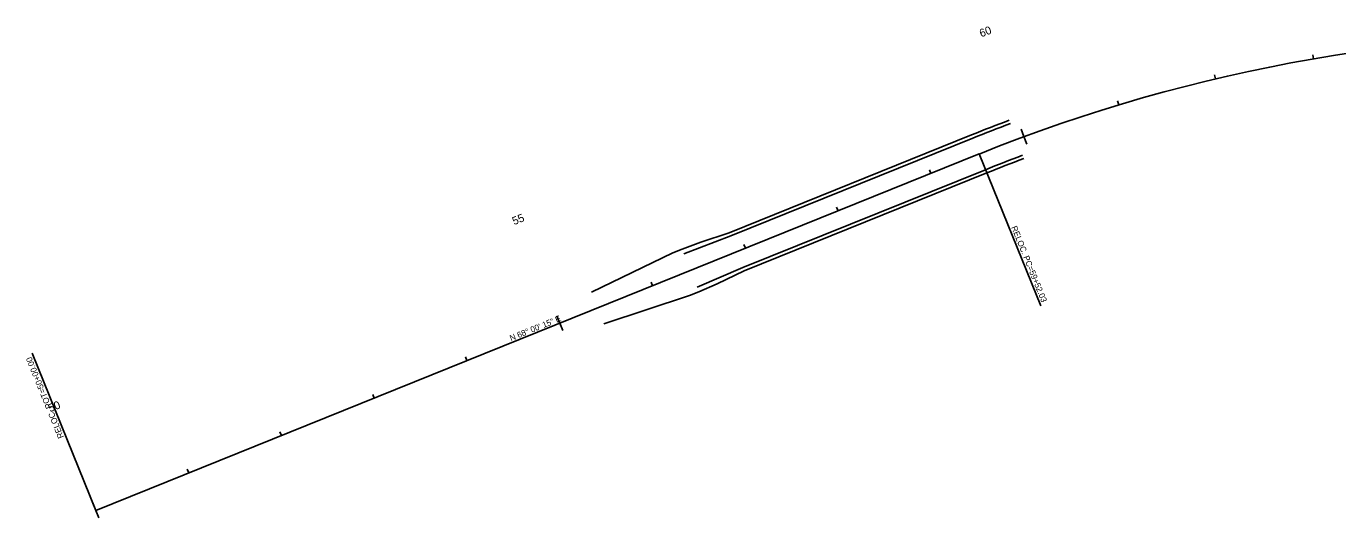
# Model space of a CAD drawing. Extents: x 1966701 to 1969286, y 1117441 to 1118086.
# Drawn here: x 1966701 to 1968012, y 1117441 to 1117933 of the extents above; entities that cross this region are included whole.
import ezdxf

# ---------------------------------------------------------------- set-up
doc = ezdxf.new("R2010")
doc.units = 0
for name, color, linetype in [('Level 19', 7, 'Continuous'), ('Level 27', 7, 'Continuous'), ('Level 35', 7, 'Continuous'), ('Level 39', 7, 'Continuous')]:
    doc.layers.add(name, color=color, linetype=linetype)

msp = doc.modelspace()

# ---------------------------------------------------------------- linework, layer by layer
at = {"layer": 'Level 19'}
for p, q in [((1967987.5, 1117899.9), (1967986.8, 1117903.8)), ((1967889.5, 1117879.8), (1967888.6, 1117883.7)), ((1967793, 1117853.8), (1967791.8, 1117857.7)), ((1967698.2, 1117822), (1967695.4, 1117829.5)), ((1967698.2, 1117822), (1967701, 1117814.5)), ((1966770.7, 1117448.1), (1967653.5, 1117804.7)), ((1967605.2, 1117785.2), (1967603.7, 1117788.9)), ((1967512.5, 1117747.7), (1967511, 1117751.5)), ((1967419.8, 1117710.3), (1967418.3, 1117714)), ((1967327.1, 1117672.8), (1967325.6, 1117676.5)), ((1967234.3, 1117635.4), (1967231.3, 1117642.8)), ((1967234.3, 1117635.4), (1967237.3, 1117628)), ((1967141.6, 1117597.9), (1967140.1, 1117601.6)), ((1967048.9, 1117560.5), (1967047.4, 1117564.2)), ((1966956.2, 1117523), (1966954.7, 1117526.7)), ((1966863.5, 1117485.6), (1966862, 1117489.3)), ((1966770.7, 1117448.1), (1966767.7, 1117455.5)), ((1966770.7, 1117448.1), (1966773.7, 1117440.7))]:
    msp.add_line(p, q, dxfattribs=at)
msp.add_arc((1968266.6, 1116286.8), 1637, 87.7266, 111.9958, dxfattribs=at)
at = {"layer": 'Level 27'}
for p, q in [((1967405.1, 1117722.7), (1967647.1, 1117820.5)), ((1967659.8, 1117788.9), (1967417.4, 1117691)), ((1967358.3, 1117704.9), (1967405.1, 1117722.7)), ((1967417.4, 1117691), (1967371.5, 1117671.4))]:
    msp.add_line(p, q, dxfattribs=at)
for radius in [1654.1, 1620.1]:
    msp.add_arc((1968266.6, 1116286.8), radius, 110.5969, 111.9958, dxfattribs=at)
at = {"layer": 'Level 35'}
for p, q in [((1967403.7, 1117725.9), (1967645.8, 1117823.7)), ((1967661.2, 1117785.7), (1967418.7, 1117687.8)), ((1967375.2, 1117716.6), (1967403.7, 1117725.9)), ((1967347.2, 1117705.8), (1967266, 1117666.5)), ((1967356.5, 1117709.5), (1967347.2, 1117705.8)), ((1967356.5, 1117709.5), (1967375.2, 1117716.6)), ((1967391.7, 1117674.6), (1967418.7, 1117687.8)), ((1967373.3, 1117666.7), (1967364.1, 1117663)), ((1967391.7, 1117674.6), (1967373.3, 1117666.7)), ((1967364.1, 1117663), (1967278.4, 1117634.8))]:
    msp.add_line(p, q, dxfattribs=at)
for radius in [1657.6, 1616.6]:
    msp.add_arc((1968266.6, 1116286.8), radius, 110.5969, 111.9958, dxfattribs=at)
at = {"layer": 'Level 39'}
for p, q in [((1967653.5, 1117804.7), (1967714.9, 1117652.6)), ((1966770.7, 1117448.1), (1966707.2, 1117605.4))]:
    msp.add_line(p, q, dxfattribs=at)

# ---------------------------------------------------------------- texts
at = {"layer": 'Level 19'}
for s, rotation, p in [('60', 20.3171, (1967655.4, 1117921.3)), ('55', 21.9958, (1967188.7, 1117733.4)), ('50', 21.9958, (1966725.1, 1117546.2))]:
    msp.add_text(s, height=8, rotation=rotation, dxfattribs=at).set_placement(p)
at = {"layer": 'Level 39'}
for s, rotation, p in [('RELOC. PC=59+52.03', 291.9958, (1967685.3, 1117731.3)), ('N 68%%d 00\' 15" E', 21.9958, (1967185.7, 1117617.4)), ('RELOC. POT=50+00.00', 111.9958, (1966738.9, 1117521.5))]:
    msp.add_text(s, height=6, rotation=rotation, dxfattribs=at).set_placement(p)

doc.saveas('drawing.dxf')
